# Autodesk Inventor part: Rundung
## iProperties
Created: 2010-04
Part Number: Rundung
Document SubType Name: Modeling
Designer: SFleischer
Density: 1 g/cm^3
Author: SFleischer
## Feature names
1. Sweeping1
